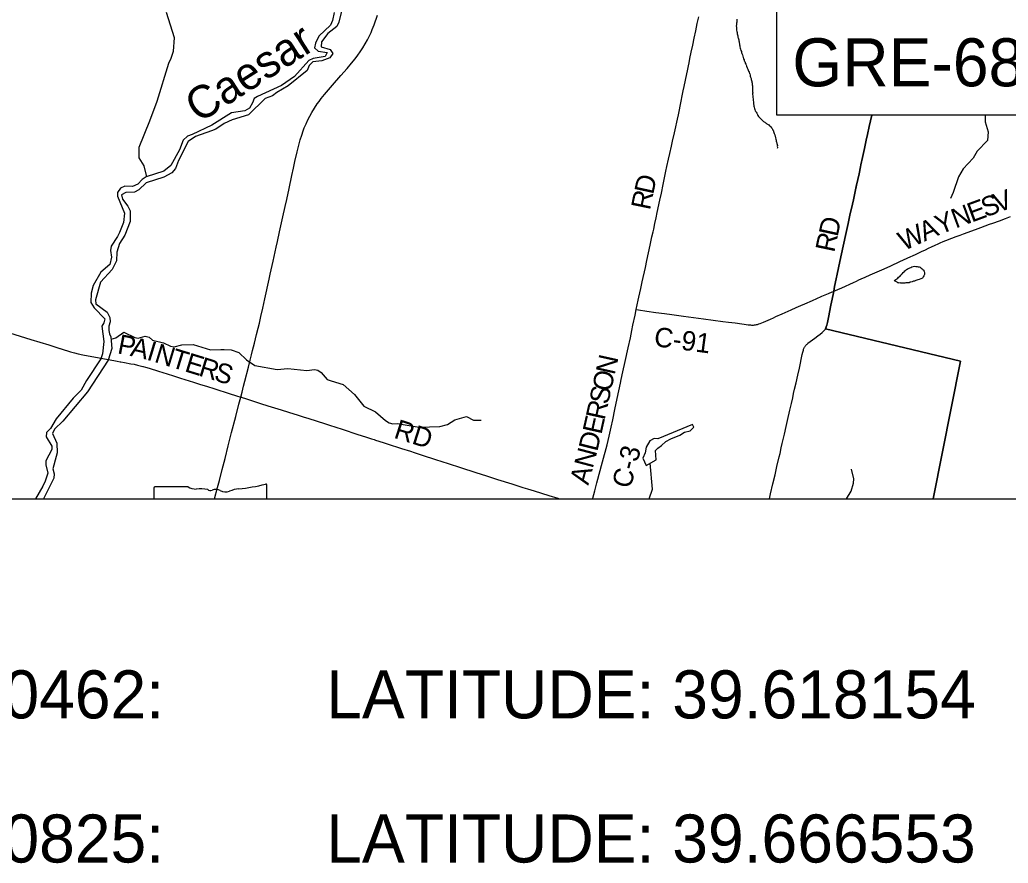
# Model space of a CAD drawing. Extents: x -1.4 to 35.4, y 0 to 22.
# Drawn here: x 10.916 to 13.799, y 11.993 to 14.45 of the extents above; entities that cross this region are included whole.
import ezdxf

# ---------------------------------------------------------------- set-up
doc = ezdxf.new("R2010")
doc.units = 0
for name, color, linetype in [('GM_X_County_Road', 7, 'Continuous'), ('GM_X_County_Road_Text', 7, 'Continuous'), ('GM_X_Interstate_Shield', 7, 'Continuous'), ('GM_X_Major_River', 7, 'Continuous'), ('GM_X_Major_River_Text', 7, 'Continuous'), ('GM_X_Minor_Lake', 7, 'Continuous'), ('GM_X_Minor_River', 7, 'Continuous'), ('GM_X_State_Route', 7, 'Continuous'), ('SC_Scratch1', 7, 'Continuous'), ('SH_Border', 7, 'Continuous'), ('SH_Data', 7, 'Continuous'), ('SH_Text', 7, 'Continuous')]:
    doc.layers.add(name, color=color, linetype=linetype)

msp = doc.modelspace()

# ---------------------------------------------------------------- linework, layer by layer
at = {"layer": 'GM_X_County_Road'}
for points in [[(12.7139, 13.6061), (12.7198, 13.633), (12.7218, 13.6421), (12.7272, 13.667), (12.7316, 13.687), (12.7404, 13.7284), (12.7448, 13.749), (12.7544, 13.794), (12.7597, 13.8176), (12.7628, 13.8322), (12.7647, 13.8407), (12.7682, 13.8571), (12.7716, 13.8728), (12.775, 13.8886), (12.783, 13.9244), (12.7872, 13.9451), (12.7923, 13.97), (12.8006, 14.0089), (12.8035, 14.0229), (12.8082, 14.0441), (12.8118, 14.061), (12.8164, 14.0817), (12.82, 14.0971), (12.8255, 14.1214), (12.8275, 14.1298), (12.8343, 14.1608), (12.8368, 14.1735), (12.8449, 14.2131), (12.8478, 14.2289), (12.8508, 14.2429), (12.8534, 14.2563), (12.8571, 14.2745), (12.8611, 14.2927), (12.8631, 14.3018), (12.8659, 14.3158), (12.8678, 14.3249), (12.8704, 14.3377), (12.8743, 14.3559), (12.8786, 14.376), (12.8831, 14.3972), (12.8875, 14.4178), (12.892, 14.4391), (12.8963, 14.4591)], [(13.29, 13.6593), (13.2924, 13.6722), (13.2973, 13.6947), (13.3004, 13.7087), (13.3083, 13.7457), (13.3177, 13.7901), (13.3262, 13.8296), (13.3322, 13.8563), (13.3373, 13.8806), (13.3443, 13.9121), (13.3472, 13.9249), (13.3525, 13.9491), (13.3557, 13.9637), (13.3603, 13.9843), (13.3638, 14.0007), (13.368, 14.0214), (13.3692, 14.0275), (13.3737, 14.0488), (13.3793, 14.0749), (13.3845, 14.0992), (13.3882, 14.1156), (13.3935, 14.1385), (13.4016, 14.1722)], [(13.29, 13.6593), (13.3131, 13.6693), (13.3476, 13.6851), (13.3561, 13.689), (13.3634, 13.6923), (13.3702, 13.6954), (13.381, 13.7002), (13.3964, 13.707), (13.4372, 13.7251), (13.4559, 13.7335), (13.4825, 13.7456), (13.5148, 13.7601), (13.5192, 13.7622), (13.5304, 13.7675), (13.5456, 13.7747), (13.5574, 13.7802), (13.5664, 13.7844), (13.5748, 13.7884), (13.586, 13.7938), (13.5944, 13.7978), (13.6006, 13.8006), (13.6085, 13.8041), (13.6166, 13.8074), (13.634, 13.814), (13.6468, 13.8187), (13.6584, 13.823), (13.6683, 13.8267), (13.7028, 13.8392), (13.719, 13.8453), (13.7441, 13.8545), (13.7535, 13.8578), (13.7733, 13.8649), (13.7906, 13.8713), (13.8057, 13.8768)], [(12.7139, 13.6061), (12.72, 13.6052), (12.7452, 13.6014), (12.7711, 13.5978), (12.7963, 13.5945), (12.8179, 13.5916), (12.8517, 13.5869), (12.9096, 13.5792), (12.9379, 13.5754), (12.9668, 13.5715), (12.9834, 13.5693), (13.0025, 13.5669), (13.0222, 13.5642), (13.029, 13.5632), (13.04, 13.5618), (13.0468, 13.5611), (13.05, 13.5609), (13.0535, 13.5607), (13.0559, 13.5609), (13.0585, 13.5611), (13.0617, 13.5615), (13.0645, 13.562), (13.0675, 13.5627), (13.0712, 13.5639), (13.0756, 13.5654), (13.0853, 13.5694), (13.0916, 13.5721), (13.0984, 13.5751), (13.1058, 13.5784), (13.1137, 13.582), (13.121, 13.5853), (13.1396, 13.5937), (13.1652, 13.6049), (13.1799, 13.6115), (13.1936, 13.6176), (13.2055, 13.6227), (13.2282, 13.6328), (13.2532, 13.644), (13.2549, 13.6448), (13.26, 13.647), (13.2749, 13.6532), (13.2853, 13.6574), (13.2887, 13.6587), (13.29, 13.6593)], [(13.1022, 13.0546), (13.1057, 13.0694), (13.1124, 13.0979), (13.1186, 13.1245), (13.1243, 13.1487), (13.1309, 13.1765), (13.1332, 13.1868), (13.1367, 13.2026), (13.1395, 13.2153), (13.1458, 13.2432), (13.1509, 13.265), (13.1553, 13.2831), (13.1621, 13.3128), (13.1664, 13.3322), (13.1702, 13.3491), (13.1728, 13.3612), (13.1757, 13.374), (13.1798, 13.3922), (13.1849, 13.4144), (13.1896, 13.4354), (13.1981, 13.4746), (13.1998, 13.4821), (13.2013, 13.488), (13.202, 13.4904), (13.2028, 13.4928), (13.2037, 13.4948), (13.2044, 13.4963), (13.2053, 13.4976), (13.2062, 13.499), (13.2071, 13.5003), (13.2081, 13.5015), (13.2093, 13.5028), (13.2103, 13.5038), (13.2119, 13.5052), (13.213, 13.5064), (13.2145, 13.5077), (13.2214, 13.513), (13.2349, 13.5229), (13.2433, 13.5292), (13.25, 13.5345), (13.2557, 13.5391), (13.2582, 13.5411), (13.2604, 13.5431), (13.2629, 13.5458), (13.2646, 13.5479), (13.2655, 13.5494), (13.266, 13.5501), (13.2674, 13.5525), (13.2684, 13.5551), (13.2699, 13.5603), (13.2709, 13.5639), (13.2717, 13.5675), (13.2746, 13.582), (13.282, 13.6186), (13.2855, 13.6356), (13.289, 13.6539), (13.29, 13.6593)], [(12.5869, 13.0546), (12.5875, 13.0568), (12.5929, 13.0778), (12.5991, 13.1006), (12.6156, 13.1618), (12.6287, 13.2117), (12.6348, 13.237), (12.641, 13.2635), (12.6455, 13.2843), (12.6517, 13.3143), (12.6584, 13.3464), (12.668, 13.3913), (12.6703, 13.4023), (12.6749, 13.4241), (12.6814, 13.4545), (12.6903, 13.4945), (12.6967, 13.5236), (12.7012, 13.5449), (12.7043, 13.5601), (12.7103, 13.59), (12.7139, 13.6061)], [(10.7465, 13.5819), (10.75, 13.5806), (10.7568, 13.5782), (10.7822, 13.5698), (10.8433, 13.551), (10.8867, 13.5378), (10.9484, 13.5187), (11.0014, 13.5027), (11.033, 13.4927)], [(11.033, 13.4927), (11.0339, 13.4924), (11.0365, 13.4916), (11.0643, 13.4832), (11.0762, 13.4798), (11.0865, 13.4772), (11.1005, 13.4741), (11.1481, 13.4651), (11.1842, 13.4585), (11.1903, 13.4575), (11.2, 13.4556), (11.2091, 13.4539), (11.2113, 13.4535), (11.2216, 13.4515), (11.2398, 13.448), (11.2501, 13.4464), (11.2591, 13.4443), (11.2671, 13.4422), (11.2751, 13.4401), (11.2761, 13.4398)], [(11.2761, 13.4398), (11.283, 13.438), (11.2937, 13.4348), (11.3204, 13.4264), (11.3465, 13.4183), (11.3649, 13.4126), (11.3847, 13.4064), (11.4224, 13.3946), (11.4437, 13.388), (11.4606, 13.3826), (11.4851, 13.3747), (11.5266, 13.3616), (11.5485, 13.3548), (11.5607, 13.351), (11.5624, 13.3504)], [(11.5624, 13.3504), (11.5651, 13.3496), (11.574, 13.3467), (11.5864, 13.3428), (11.6183, 13.3326), (11.6396, 13.3257), (11.6781, 13.3136), (11.6995, 13.3071), (11.7285, 13.2981), (11.743, 13.2936), (11.7595, 13.2885), (11.7802, 13.2817), (11.8079, 13.2726), (11.8192, 13.2689), (11.8564, 13.2571), (11.9025, 13.2421), (11.9114, 13.2392), (11.9273, 13.2341), (11.9356, 13.2315), (11.9421, 13.2294), (11.9492, 13.227), (11.9533, 13.2257), (11.9758, 13.2185), (11.9994, 13.2108), (12.0177, 13.2048), (12.0296, 13.2011), (12.0557, 13.1929), (12.0663, 13.1895), (12.0899, 13.1818), (12.1289, 13.1692), (12.1656, 13.1572), (12.201, 13.1457), (12.2466, 13.1311), (12.2773, 13.1212), (12.3093, 13.1111), (12.3514, 13.0977), (12.3828, 13.0879), (12.3971, 13.0836), (12.4161, 13.0776), (12.4593, 13.0639), (12.4848, 13.056), (12.4892, 13.0546)]]:
    msp.add_lwpolyline(points, dxfattribs=at)
at = {"layer": 'GM_X_Interstate_Shield'}
msp.add_line((11.407, 13.0892), (11.3104, 13.0892), dxfattribs=at)
msp.add_lwpolyline([(11.3072, 13.0857), (11.3072, 13.0546), (11.6368, 13.0546), (11.6368, 13.0943)], dxfattribs=at)
for centre, major_axis, start_param, end_param in [((11.311, 13.0862), (0.00382, 0), 1.727492, 3.291633), ((11.43, 13.1124), (0.037, 0), 4.042888, 4.731792), ((11.5194, 13.362), (0.3495, 0), 4.814394, 5.042369), ((11.6331, 13.0946), (0.00367, 0), 6.197627, 7.989034), ((11.4422, 12.9768), (0.133, 0), 1.404758, 1.657859), ((11.4724, 13.0872), (0.0107, 0), 3.836095, 5.185415), ((11.4881, 13.0641), (0.0222, 0), 0.950623, 2.079405), ((11.5168, 13.0958), (0.0267, 0), 4.08156, 5.145723), ((11.564, 13.0281), (0.0703, 0), 1.699012, 2.107814)]:
    msp.add_ellipse(centre, major_axis=major_axis, ratio=0.8, start_param=start_param, end_param=end_param, dxfattribs=at)
at = {"layer": 'GM_X_Major_River'}
for points in [[(11.833, 14.4719), (11.8279, 14.448), (11.8226, 14.4345), (11.7884, 14.4022), (11.7781, 14.3819), (11.7755, 14.3687), (11.7867, 14.3589), (11.8124, 14.3553), (11.8072, 14.3429), (11.7721, 14.3372), (11.7587, 14.3318), (11.7169, 14.2849), (11.6794, 14.2591), (11.6095, 14.2273), (11.5999, 14.2211), (11.595, 14.2083), (11.5859, 14.1929), (11.5728, 14.1852), (11.5339, 14.1793), (11.4764, 14.1437), (11.4188, 14.1162), (11.4057, 14.1108), (11.3922, 14.0993), (11.3824, 14.0714), (11.357, 14.0256), (11.3361, 14.0097), (11.2848, 13.9923), (11.2736, 13.9853), (11.26, 13.9716), (11.2454, 13.9643), (11.223, 13.966), (11.2095, 13.9594), (11.2009, 13.9475), (11.2014, 13.9364), (11.2215, 13.887), (11.2186, 13.86), (11.2069, 13.8307), (11.2013, 13.8186), (11.1832, 13.7905), (11.181, 13.7777), (11.1836, 13.7582), (11.1793, 13.737), (11.1525, 13.7145), (11.13, 13.6762), (11.1245, 13.6535), (11.1235, 13.6266), (11.1327, 13.6108), (11.1638, 13.5785), (11.1617, 13.5675), (11.1558, 13.5578), (11.1612, 13.5124), (11.1577, 13.4768), (11.1524, 13.4621), (11.1107, 13.3992), (11.0956, 13.3714), (11.0722, 13.3476), (11.0222, 13.2872), (11.006, 13.2598), (10.9943, 13.2475), (10.9928, 13.2347), (11.0093, 13.208), (11.0095, 13.1985), (10.9924, 13.1655), (10.9921, 13.1537), (10.9984, 13.1296), (10.9902, 13.1059), (10.9834, 13.0916), (10.9624, 13.0546)], [(11.854, 14.4756), (11.8471, 14.4434), (11.8404, 14.4307), (11.8145, 14.4103), (11.7956, 14.3857), (11.7949, 14.3716), (11.821, 14.3634), (11.8287, 14.3522), (11.8208, 14.3399), (11.7974, 14.3305), (11.7704, 14.3281), (11.7598, 14.317), (11.7546, 14.3026), (11.6992, 14.2576), (11.6657, 14.2386), (11.6536, 14.229), (11.6318, 14.2211), (11.5836, 14.1732), (11.5353, 14.1591), (11.5119, 14.1482), (11.4883, 14.132), (11.4753, 14.1266), (11.4289, 14.1106), (11.4073, 14.0955), (11.3786, 14.0407), (11.3705, 14.0166), (11.3596, 14.0039), (11.3365, 13.9915), (11.2844, 13.9752), (11.2638, 13.9544), (11.2503, 13.9482), (11.2252, 13.9469), (11.2133, 13.9407), (11.2153, 13.9281), (11.2315, 13.9072), (11.2384, 13.8934), (11.2384, 13.8626), (11.2223, 13.8231), (11.2066, 13.7987), (11.1991, 13.7734), (11.1986, 13.7484), (11.1858, 13.7228), (11.1519, 13.686), (11.137, 13.6342), (11.1382, 13.6224), (11.1708, 13.5981), (11.1788, 13.5827), (11.18, 13.5702), (11.1755, 13.5577), (11.1756, 13.5452), (11.1781, 13.5356), (11.182, 13.526), (11.185, 13.4925), (11.174, 13.4589), (11.1141, 13.366), (11.0422, 13.2803), (11.0173, 13.2573), (11.0121, 13.2452), (11.024, 13.2168), (11.0252, 13.1883), (11.0219, 13.1774), (11.0127, 13.1422), (11.0166, 13.1273), (11.0159, 13.1148), (10.9853, 13.0546)]]:
    msp.add_lwpolyline(points, dxfattribs=at)
at = {"layer": 'GM_X_Minor_Lake'}
for points in [[(13.4671, 13.69), (13.4684, 13.6914), (13.4768, 13.6974), (13.4787, 13.7001), (13.4814, 13.702), (13.4833, 13.7031), (13.4852, 13.7061), (13.4875, 13.7084), (13.489, 13.7103), (13.4925, 13.714), (13.4948, 13.7159), (13.4975, 13.7189), (13.5001, 13.7212), (13.5024, 13.7227), (13.5043, 13.7238), (13.507, 13.7253), (13.5097, 13.7265), (13.512, 13.7272), (13.5146, 13.7287), (13.5173, 13.7302), (13.5211, 13.7313), (13.5253, 13.732), (13.5295, 13.7313), (13.5333, 13.7316), (13.5363, 13.7308), (13.539, 13.7308), (13.5416, 13.7293), (13.545, 13.727), (13.5481, 13.725), (13.5492, 13.7231), (13.5522, 13.7208), (13.5526, 13.7189), (13.5537, 13.7166), (13.5548, 13.7125), (13.5548, 13.7102), (13.5548, 13.7079), (13.5529, 13.7041), (13.551, 13.7015), (13.5483, 13.6977), (13.5441, 13.6954), (13.5391, 13.6932), (13.5353, 13.6921), (13.5323, 13.6913), (13.5288, 13.6902), (13.5254, 13.6891), (13.522, 13.6884), (13.5182, 13.6872), (13.5151, 13.6861), (13.5121, 13.6854), (13.5094, 13.6843), (13.506, 13.6843), (13.5029, 13.6836), (13.5003, 13.6836), (13.4976, 13.6832), (13.4949, 13.6829), (13.493, 13.6829), (13.4911, 13.6829), (13.4877, 13.6829), (13.4858, 13.6833), (13.4832, 13.6837), (13.4809, 13.6833), (13.479, 13.6837), (13.4771, 13.6841), (13.4748, 13.6853), (13.4671, 13.69)], [(12.7716, 13.1679), (12.7703, 13.1953), (12.7769, 13.2019), (12.7877, 13.2097), (12.8005, 13.2219), (12.815, 13.2292), (12.8411, 13.2403), (12.8549, 13.2487), (12.8713, 13.2529), (12.8814, 13.2633), (12.8782, 13.271), (12.7771, 13.2289), (12.7665, 13.2303), (12.7531, 13.2238), (12.7428, 13.2046), (12.7402, 13.1884), (12.7334, 13.1733), (12.7424, 13.1518)], [(12.7424, 13.1518), (12.7716, 13.1679)]]:
    msp.add_lwpolyline(points, dxfattribs=at)
at = {"layer": 'GM_X_Minor_River'}
for points in [[(11.2867, 13.993), (11.2793, 14.0249), (11.2646, 14.0477), (11.2645, 14.0792), (11.2954, 14.1556), (11.3171, 14.2129), (11.351, 14.3241), (11.3577, 14.3384), (11.3642, 14.3588), (11.3677, 14.3974), (11.3439, 14.4717)], [(13.0069, 14.4523), (13.0069, 14.4496), (13.0069, 14.4466), (13.0069, 14.4439), (13.0065, 14.4409), (13.0061, 14.4382), (13.0061, 14.4363), (13.0057, 14.4321), (13.006, 14.4302), (13.0064, 14.4276), (13.006, 14.4241), (13.0063, 14.42), (13.0071, 14.4162), (13.0078, 14.4135), (13.0082, 14.4097), (13.0089, 14.4063), (13.01, 14.4032), (13.0104, 14.3998), (13.0111, 14.3975), (13.0119, 14.3948), (13.0126, 14.3922), (13.013, 14.3887), (13.0137, 14.3865), (13.0152, 14.3773), (13.0155, 14.3743), (13.0163, 14.3712), (13.017, 14.3674), (13.0181, 14.3644), (13.0193, 14.361), (13.0204, 14.3583), (13.0211, 14.3552), (13.0222, 14.3522), (13.0234, 14.348), (13.0245, 14.3446), (13.0256, 14.3404)], [(13.0256, 14.3404), (13.0267, 14.337), (13.0282, 14.3339), (13.0286, 14.3309), (13.0301, 14.3286), (13.0312, 14.3263), (13.0319, 14.3236), (13.0331, 14.3213), (13.0342, 14.3187), (13.0353, 14.3152), (13.0376, 14.3103), (13.039, 14.3065), (13.0405, 14.3034), (13.0417, 14.3004), (13.0428, 14.2973), (13.0443, 14.2943), (13.0447, 14.2924), (13.0462, 14.2889), (13.0465, 14.2863), (13.0473, 14.2828), (13.0488, 14.2794), (13.0495, 14.2764), (13.0502, 14.2733), (13.0506, 14.2706), (13.0513, 14.2684), (13.0517, 14.2657), (13.0521, 14.2627), (13.0524, 14.2604), (13.0528, 14.2581), (13.0528, 14.255), (13.0528, 14.2524), (13.0531, 14.249), (13.0531, 14.2467), (13.0527, 14.2433), (13.0531, 14.2406), (13.0534, 14.2379), (13.053, 14.2349), (13.0541, 14.2265), (13.0537, 14.2235), (13.0544, 14.2201), (13.0548, 14.2155), (13.0555, 14.2117), (13.0555, 14.2079), (13.0562, 14.2048), (13.057, 14.2022), (13.057, 14.1984), (13.0581, 14.1953), (13.0592, 14.1919), (13.0599, 14.1889), (13.061, 14.1854), (13.0626, 14.1831), (13.0637, 14.1808), (13.0652, 14.1782), (13.0663, 14.1759), (13.0674, 14.174), (13.0689, 14.1717), (13.0701, 14.169), (13.0723, 14.1667), (13.0742, 14.1644), (13.0761, 14.1625), (13.078, 14.1606), (13.0799, 14.1591), (13.0833, 14.156), (13.0852, 14.1541), (13.0871, 14.1529), (13.089, 14.1518), (13.0905, 14.1499), (13.0927, 14.1487), (13.095, 14.1476), (13.0984, 14.1449), (13.1003, 14.1441), (13.1026, 14.1414), (13.1045, 14.1399), (13.1064, 14.1387), (13.1086, 14.1353), (13.1101, 14.1334), (13.1113, 14.1315), (13.1124, 14.1284), (13.1139, 14.1265), (13.1146, 14.1246), (13.1154, 14.1219), (13.1161, 14.1193), (13.1176, 14.1155), (13.1202, 14.1059), (13.1213, 14.1029), (13.1221, 14.0998), (13.1224, 14.0968), (13.1232, 14.0941), (13.1239, 14.0918), (13.1239, 14.0896), (13.125, 14.0865), (13.1254, 14.0839), (13.125, 14.0812), (13.1254, 14.0789), (13.1257, 14.077), (13.1253, 14.0751)], [(13.7309, 14.1722), (13.7315, 14.1532), (13.7403, 14.1241), (13.7386, 14.0984), (13.708, 14.0675), (13.6962, 14.0473), (13.6674, 14.0164), (13.654, 13.9924), (13.6383, 13.9472), (13.6301, 13.9291)], [(11.1826, 13.5197), (11.1965, 13.5232), (11.2192, 13.5401), (11.2515, 13.5249), (11.2617, 13.5228), (11.282, 13.528), (11.2933, 13.5258), (11.303, 13.5172), (11.3354, 13.5093), (11.3557, 13.4993), (11.3663, 13.4975), (11.3892, 13.5035), (11.4222, 13.5042), (11.472, 13.4882), (11.5027, 13.4898), (11.5122, 13.4899), (11.5331, 13.4883), (11.5549, 13.4813), (11.5772, 13.4599), (11.6012, 13.443), (11.6666, 13.4316), (11.6977, 13.4343), (11.7534, 13.4284), (11.7755, 13.4313), (11.7853, 13.4296), (11.795, 13.4225), (11.8124, 13.4024), (11.8245, 13.3979), (11.8595, 13.388), (11.8927, 13.3587), (11.9193, 13.3243), (11.9531, 13.3083), (11.9825, 13.2829), (11.9937, 13.2754), (12.0043, 13.2725), (12.0169, 13.2741), (12.0807, 13.2631), (12.1415, 13.2651), (12.1633, 13.2714), (12.1852, 13.2842), (12.2188, 13.2944), (12.2394, 13.2833), (12.2618, 13.2835)], [(12.7513, 13.0546), (12.7614, 13.083), (12.7545, 13.1585)], [(13.3273, 13.0546), (13.3403, 13.0763), (13.3473, 13.1001), (13.348, 13.113), (13.3413, 13.1408)]]:
    msp.add_lwpolyline(points, dxfattribs=at)
at = {"layer": 'GM_X_State_Route'}
for points in [[(11.7171, 14.0321), (11.7181, 14.037), (11.7249, 14.066), (11.7297, 14.0853), (11.7341, 14.1009), (11.7384, 14.1146), (11.7425, 14.1263), (11.746, 14.1357), (11.7509, 14.1471), (11.7561, 14.1584), (11.7618, 14.1695), (11.7676, 14.1799), (11.7758, 14.1931), (11.7839, 14.2056), (11.789, 14.2127), (11.795, 14.2207), (11.8044, 14.2323), (11.8279, 14.2597), (11.8529, 14.2881), (11.8706, 14.3082), (11.8838, 14.3238), (11.8938, 14.3364), (11.902, 14.3474), (11.9088, 14.357), (11.9162, 14.3684), (11.9233, 14.3801), (11.93, 14.392), (11.9359, 14.4035), (11.9406, 14.4137), (11.9443, 14.4222), (11.9497, 14.436), (11.9598, 14.4635)], [(11.5689, 13.3832), (11.5723, 13.3969), (11.5833, 13.4383), (11.5885, 13.4588), (11.5923, 13.4745), (11.5952, 13.4866), (11.6007, 13.5082), (11.607, 13.5329), (11.6114, 13.5516), (11.6149, 13.5667), (11.6192, 13.5861), (11.6246, 13.6104), (11.6305, 13.6371), (11.6431, 13.6941), (11.6464, 13.7093), (11.655, 13.7468), (11.6641, 13.7874), (11.6677, 13.8038), (11.674, 13.8323), (11.6836, 13.876), (11.6899, 13.9058), (11.6945, 13.927), (11.7017, 13.9592), (11.7097, 13.9962), (11.7141, 14.0175), (11.7171, 14.0321)], [(11.4965, 13.1007), (11.4984, 13.1075), (11.5066, 13.1399), (11.5148, 13.1724), (11.5243, 13.2091), (11.534, 13.2477), (11.546, 13.2947), (11.5552, 13.3301), (11.5607, 13.351), (11.5644, 13.3656), (11.5689, 13.3832)], [(11.4843, 13.0546), (11.4929, 13.0871), (11.4965, 13.1007)]]:
    msp.add_lwpolyline(points, dxfattribs=at)
at = {"layer": 'SC_Scratch1'}
msp.add_line((-1.4282, 13.0546), (35.3749, 13.0546), dxfattribs=at)
for points in [[(9.6299, 13.0546), (13.5799, 13.0546), (13.6592, 13.4559), (13.2653, 13.5499), (13.2658, 13.5506), (13.2671, 13.553), (13.2682, 13.5556), (13.2697, 13.5609), (13.2707, 13.5644), (13.2715, 13.568), (13.2744, 13.5826), (13.2818, 13.6191), (13.2852, 13.6361), (13.2888, 13.6544), (13.2898, 13.6598), (13.2922, 13.6728), (13.2971, 13.6952), (13.3002, 13.7092), (13.308, 13.7463), (13.3175, 13.7906), (13.326, 13.8301), (13.3319, 13.8568), (13.3371, 13.8811), (13.3441, 13.9127), (13.347, 13.9254), (13.3523, 13.9497), (13.3555, 13.9642), (13.3601, 13.9848), (13.3635, 14.0013), (13.3678, 14.0219), (13.369, 14.028), (13.3735, 14.0493), (13.3791, 14.0754), (13.3843, 14.0997), (13.3879, 14.1161), (13.3933, 14.1391), (13.4012, 14.1722)], [(13.4012, 14.1722), (13.3933, 14.1391), (13.3879, 14.1161), (13.3843, 14.0997), (13.3791, 14.0754), (13.3735, 14.0493), (13.369, 14.028), (13.3678, 14.0219), (13.3635, 14.0013), (13.3601, 13.9848), (13.3555, 13.9642), (13.3523, 13.9497), (13.347, 13.9254), (13.3441, 13.9127), (13.3371, 13.8811), (13.3319, 13.8568), (13.326, 13.8301), (13.3175, 13.7906), (13.308, 13.7463), (13.3002, 13.7092), (13.2971, 13.6952), (13.2922, 13.6728), (13.2898, 13.6598), (13.2888, 13.6544), (13.2852, 13.6361), (13.2818, 13.6191), (13.2744, 13.5826), (13.2715, 13.568), (13.2707, 13.5644), (13.2697, 13.5609), (13.2682, 13.5556), (13.2671, 13.553), (13.2658, 13.5506), (13.2653, 13.5499), (13.6592, 13.4559), (13.5799, 13.0546), (16.4299, 13.0546)]]:
    msp.add_lwpolyline(points, dxfattribs=at)
at = {"layer": 'SH_Border'}
msp.add_lwpolyline([(9.6299, 19.8546), (9.6299, 13.0546), (16.4299, 13.0546), (16.4299, 19.8546)], close=True, dxfattribs=at)
at = {"layer": 'SH_Data'}
msp.add_lwpolyline([(13.1243, 14.4922), (14.3943, 14.4922), (14.3943, 14.3747), (15.1442, 14.7096), (14.3943, 14.2522), (14.3943, 14.1722), (13.1243, 14.1722)], close=True, dxfattribs=at)

# ---------------------------------------------------------------- texts
at = {"layer": 'GM_X_County_Road_Text'}
for s, height, rotation, p in [('D', 0.0568, 77.7248, (12.7631, 13.9392)), ('R', 0.0568, 78.3357, (12.7537, 13.8937)), ('V', 0.0568, 20.2539, (13.7679, 13.8872)), ('E', 0.0568, 20.2486, (13.6921, 13.8592)), ('S', 0.0568, 20.2528, (13.732, 13.8739)), ('Y', 0.0568, 21.7439, (13.5991, 13.8235)), ('N', 0.0568, 20.3083, (13.6452, 13.8419)), ('D', 0.0568, 77.762, (13.3009, 13.816)), ('A', 0.0568, 23.9984, (13.554, 13.8034)), ('W', 0.0568, 24.6457, (13.4943, 13.776)), ('R', 0.0568, 78.0808, (13.2912, 13.7704)), ('C-91', 0.05682, 352.4491, (12.7635, 13.4997)), ('P', 0.0568, 348.937, (11.1987, 13.4787)), ('A', 0.0568, 347.1539, (11.2359, 13.4714)), ('I', 0.0568, 343.1475, (11.2836, 13.4606)), ('N', 0.0568, 342.9567, (11.3059, 13.4538)), ('T', 0.0568, 342.9408, (11.3537, 13.4392)), ('E', 0.0568, 342.9379, (11.3943, 13.4267)), ('R', 0.0568, 342.941, (11.4349, 13.4142)), ('N', 0.0568, 77.5297, (12.6507, 13.4135)), ('S', 0.0568, 342.9385, (11.4796, 13.4005)), ('O', 0.0568, 77.5312, (12.6399, 13.3647)), ('S', 0.0568, 77.5335, (12.6316, 13.3272)), ('R', 0.0568, 77.5325, (12.6215, 13.2817)), ('E', 0.0568, 77.3532, (12.6122, 13.24)), ('RD', 0.05682, 342.3264, (12.0043, 13.2329)), ('D', 0.0568, 76.2168, (12.6, 13.1903)), ('N', 0.0568, 75.1778, (12.5869, 13.1408)), ('C-3', 0.05682, 75.1859, (12.697, 13.0819)), ('A', 0.0568, 75.0674, (12.574, 13.0924))]:
    msp.add_text(s, height=height, rotation=rotation, dxfattribs=at).set_placement(p)
at = {"layer": 'GM_X_Major_River_Text'}
msp.add_text('Caesar', height=0.09469, rotation=32.5146, dxfattribs=at).set_placement((11.4379, 14.1474))
at = {"layer": 'SH_Data'}
msp.add_text('GRE-68-0462', height=0.14, dxfattribs=at).set_placement((13.1691, 14.2564))
at = {"layer": 'SH_Text'}
for s, p in [('GRE-68-0462:', (10.1299, 12.4146)), ('LATITUDE: 39.618154', (11.8099, 12.4146)), ('GRE-42-0825:', (10.1299, 11.9946)), ('LATITUDE: 39.666553', (11.8099, 11.9946))]:
    msp.add_text(s, height=0.14, dxfattribs=at).set_placement(p)

doc.saveas('drawing.dxf')
